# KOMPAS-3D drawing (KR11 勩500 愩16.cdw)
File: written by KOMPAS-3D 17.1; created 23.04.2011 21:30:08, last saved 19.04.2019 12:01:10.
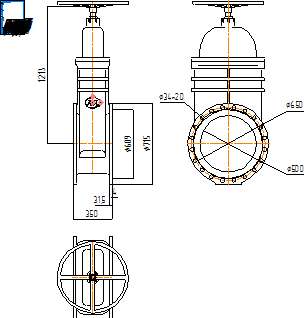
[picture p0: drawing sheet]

Sheet 1: A4, portrait

Title block, sheet 1: name: KR11 Ду500 Ру16; material: Внимание! Данный продукт является объектом авторского права ООО «Торговый Дом АДЛ». / Запрещается изменение, копирование, распространение / (в том числе путем копирования на другие сайты и ресурсы в Интернете) / или любое иное использование информации и объектов без предварительного / согласия правообладателя (ООО «Торговый Дом АДЛ»).; scale: 1:1; sheets: 1; organisation: ООО "Торговый дом АДЛ"; sheet format: A4; stored path: \\adlc.lan\data\АДЛ_ПКД\3D-модели\ADL production\Клиновые задвижки серии KR ГРАНАР\Клиновые задвижки KR11\KOMPAS 2D\KR11 Ду500 Ру16.cdw

Views: Спереди 4, Проекционный вид 5, Проекционный вид 6
Dimensions and other numbers on the sheet: 350; 609; 715; 1213; 4; 31,5; 650; 500; 34; 1:1; 1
